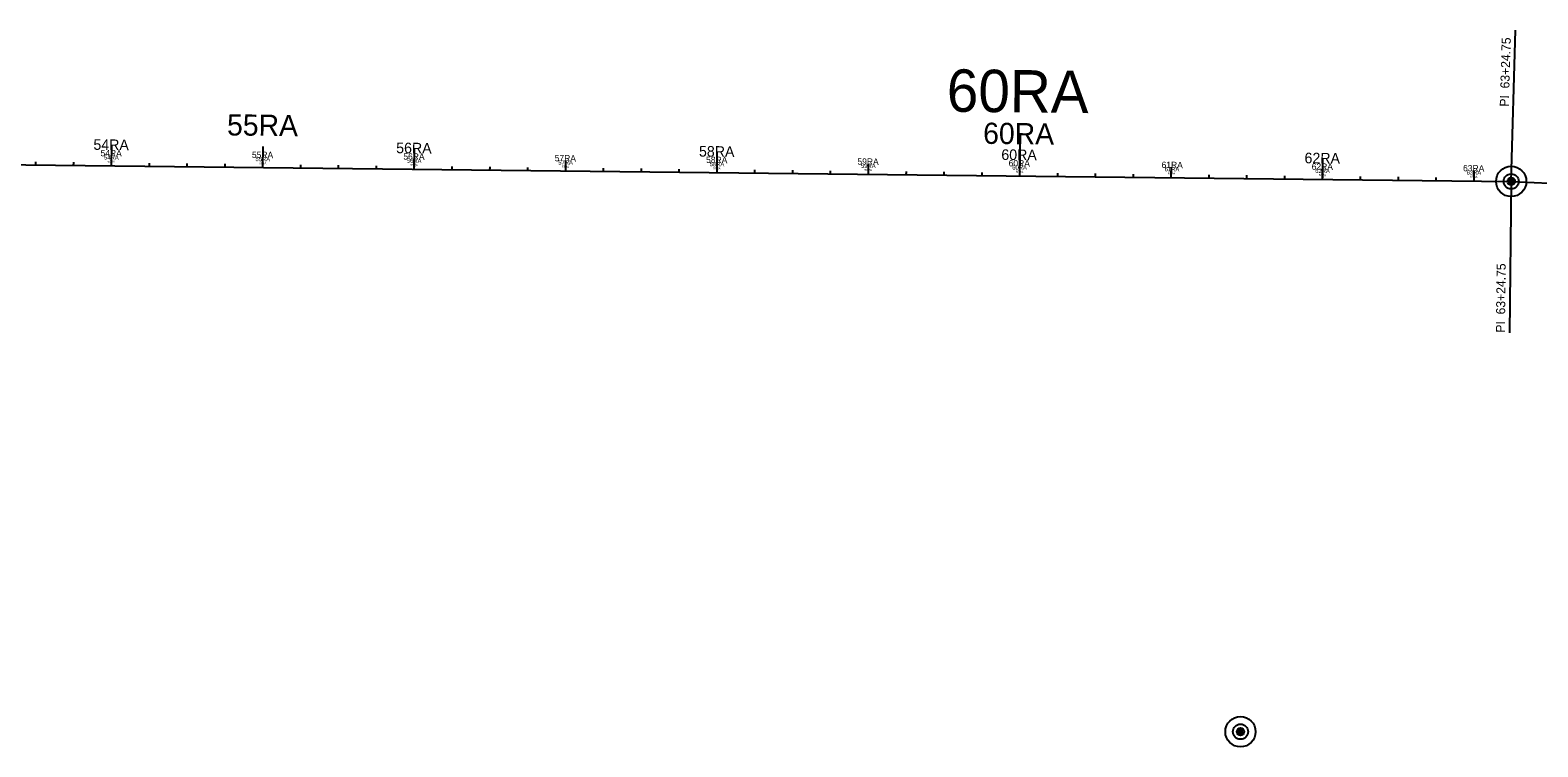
# Model space of a CAD drawing. Extents: x 564646 to 607088, y 225853 to 261760.
# Drawn here: x 599296 to 600292, y 254603 to 255076 of the extents above; entities that cross this region are included whole.
import ezdxf

# ---------------------------------------------------------------- set-up
doc = ezdxf.new("R2010")
doc.units = 0
for name, color, linetype in [('B_CONC_HIDDEN_LT', 7, 'Continuous'), ('B_CONST', 7, 'Continuous'), ('B_EXIST', 7, 'Continuous'), ('B_TEXT', 7, 'Continuous'), ('E-Easements', 7, 'Continuous'), ('E-Property Lines', 7, 'Continuous'), ('E_ALI_100', 7, 'Continuous'), ('E_RW_CorporateLimits', 7, 'Continuous'), ('E_RW_EasementUtility_Text', 7, 'Continuous'), ('E_WTR_FlowLine', 7, 'Continuous'), ('EMCS_SURVEY_PT CODES', 7, 'Continuous'), ('EMCS_SURVEY_PT ELEV', 7, 'Continuous'), ('EMCS_SURVEY_PT NOTES', 7, 'Continuous'), ('Level 33', 7, 'Continuous'), ('P-Easements Floodplain', 7, 'Continuous'), ('P-Easements Temporary', 7, 'Continuous'), ('P_ALI_100_Tic', 7, 'Continuous'), ('P_ALI_20', 7, 'Continuous'), ('P_ALI_50', 7, 'Continuous'), ('P_RW_AccessPreviousProject Txt', 7, 'Continuous'), ('P_RW_EasementPerm', 7, 'Continuous'), ('P_RW_EasementTemp', 7, 'Continuous'), ('P_RW_PropertyConnector', 7, 'Continuous'), ('P_RW_Proposed', 7, 'Continuous'), ('P_WAL', 7, 'Continuous')]:
    doc.layers.add(name, color=color, linetype=linetype)

msp = doc.modelspace()

# ---------------------------------------------------------------- linework, layer by layer
at = {"layer": 'B_CONC_HIDDEN_LT'}
for p, q in [((597615.91, 255005.79), (600274.63, 254976.34)), ((600274.63, 254976.34), (602948.94, 254849.85))]:
    msp.add_line(p, q, dxfattribs=at)
at = {"layer": 'B_CONST'}
for centre in [(600274.63, 254976.34), (600095.84, 254612.72)]:
    msp.add_circle(centre, 1.5, dxfattribs=at)
at = {"layer": 'B_EXIST'}
for centre in [(600274.63, 254976.34), (600095.84, 254612.72)]:
    msp.add_circle(centre, 5, dxfattribs=at)
at = {"layer": 'B_TEXT'}
msp.add_lwpolyline([(600274.63, 254976.34), (600273.52, 254876.35)], dxfattribs=at)
at = {"layer": 'E-Easements'}
for centre in [(600274.63, 254976.34), (600095.84, 254612.72)]:
    msp.add_circle(centre, 2.5, dxfattribs=at)
at = {"layer": 'E_ALI_100'}
for points in [[(599349.96, 254989.38), (599349.93, 254986.58)], [(599299.95, 254988.54), (599299.94, 254987.14)], [(599324.95, 254988.26), (599324.94, 254986.86)], [(599374.95, 254987.71), (599374.93, 254986.31)], [(599399.95, 254987.43), (599399.93, 254986.03)], [(599424.94, 254987.15), (599424.93, 254985.75)], [(599449.96, 254988.27), (599449.93, 254985.48)], [(599474.94, 254986.6), (599474.93, 254985.2)], [(599499.94, 254986.32), (599499.92, 254984.92)], [(599524.94, 254986.04), (599524.92, 254984.64)], [(599549.95, 254987.17), (599549.92, 254984.37)], [(599574.94, 254985.49), (599574.92, 254984.09)], [(599599.93, 254985.21), (599599.92, 254983.81)], [(599624.93, 254984.94), (599624.92, 254983.54)], [(599649.95, 254986.06), (599649.92, 254983.26)], [(599674.93, 254984.38), (599674.91, 254982.98)], [(599699.93, 254984.11), (599699.91, 254982.71)], [(599724.93, 254983.83), (599724.91, 254982.43)], [(599749.94, 254984.95), (599749.91, 254982.15)], [(599774.92, 254983.28), (599774.91, 254981.88)], [(599799.92, 254983), (599799.91, 254981.6)], [(599824.92, 254982.72), (599824.9, 254981.32)], [(599849.93, 254983.84), (599849.9, 254981.04)], [(599874.92, 254982.17), (599874.9, 254980.77)], [(599899.92, 254981.89), (599899.9, 254980.49)], [(599924.91, 254981.61), (599924.9, 254980.21)], [(599949.93, 254982.74), (599949.9, 254979.94)], [(599974.91, 254981.06), (599974.9, 254979.66)], [(599999.91, 254980.78), (599999.89, 254979.38)], [(600024.91, 254980.51), (600024.89, 254979.11)], [(600049.92, 254981.63), (600049.89, 254978.83)], [(600074.9, 254979.95), (600074.89, 254978.55)], [(600099.9, 254979.68), (600099.89, 254978.28)], [(600124.9, 254979.4), (600124.89, 254978)], [(600149.92, 254980.52), (600149.88, 254977.72)], [(600174.9, 254978.84), (600174.88, 254977.44)], [(600249.91, 254979.41), (600249.88, 254976.61)], [(600199.9, 254978.57), (600199.88, 254977.17)], [(600224.9, 254978.29), (600224.88, 254976.89)], [(600274.94, 254977.73), (600274.88, 254976.33)]]:
    msp.add_lwpolyline(points, dxfattribs=at)
at = {"layer": 'E_WTR_FlowLine'}
for centre in [(600274.63, 254976.34), (600095.84, 254612.72)]:
    msp.add_circle(centre, 0.5, dxfattribs=at)
at = {"layer": 'EMCS_SURVEY_PT CODES'}
for p, q in [((597615.91, 255005.79), (600274.63, 254976.34)), ((600274.63, 254976.34), (602948.94, 254849.85))]:
    msp.add_line(p, q, dxfattribs=at)
at = {"layer": 'EMCS_SURVEY_PT ELEV'}
for p, q in [((597615.91, 255005.79), (600274.63, 254976.34)), ((600274.63, 254976.34), (602948.94, 254849.85))]:
    msp.add_line(p, q, dxfattribs=at)
at = {"layer": 'Level 33'}
for points in [[(599299.94, 254987.84), (599299.94, 254987.14)], [(599324.94, 254987.56), (599324.94, 254986.86)], [(599349.95, 254987.98), (599349.93, 254986.58)], [(599374.94, 254987.01), (599374.93, 254986.31)], [(599399.94, 254986.73), (599399.93, 254986.03)], [(599424.94, 254986.45), (599424.93, 254985.75)], [(599449.94, 254986.87), (599449.93, 254985.48)], [(599474.93, 254985.9), (599474.93, 254985.2)], [(599499.93, 254985.62), (599499.92, 254984.92)], [(599524.93, 254985.34), (599524.92, 254984.64)], [(599549.94, 254985.77), (599549.92, 254984.37)], [(599574.93, 254984.79), (599574.92, 254984.09)], [(599599.93, 254984.51), (599599.92, 254983.81)], [(599624.92, 254984.24), (599624.92, 254983.54)], [(599649.93, 254984.66), (599649.92, 254983.26)], [(599674.92, 254983.68), (599674.91, 254982.98)], [(599699.92, 254983.41), (599699.91, 254982.71)], [(599724.92, 254983.13), (599724.91, 254982.43)], [(599749.92, 254983.55), (599749.91, 254982.15)], [(599774.92, 254982.58), (599774.91, 254981.88)], [(599799.91, 254982.3), (599799.91, 254981.6)], [(599824.91, 254982.02), (599824.9, 254981.32)], [(599849.92, 254982.44), (599849.9, 254981.04)], [(599874.91, 254981.47), (599874.9, 254980.77)], [(599899.91, 254981.19), (599899.9, 254980.49)], [(599924.91, 254980.91), (599924.9, 254980.21)], [(599949.91, 254981.34), (599949.9, 254979.94)], [(599974.9, 254980.36), (599974.9, 254979.66)], [(599999.9, 254980.08), (599999.89, 254979.38)], [(600024.9, 254979.81), (600024.89, 254979.11)], [(600049.91, 254980.23), (600049.89, 254978.83)], [(600074.9, 254979.25), (600074.89, 254978.55)], [(600099.9, 254978.98), (600099.89, 254978.28)], [(600149.9, 254979.12), (600149.88, 254977.72)], [(600124.89, 254978.7), (600124.89, 254978)], [(600174.89, 254978.14), (600174.88, 254977.44)], [(600199.89, 254977.87), (600199.88, 254977.17)], [(600224.89, 254977.59), (600224.88, 254976.89)], [(600249.89, 254978.01), (600249.88, 254976.61)], [(600274.91, 254977.03), (600274.88, 254976.33)]]:
    msp.add_lwpolyline(points, dxfattribs=at)
at = {"layer": 'P-Easements Floodplain'}
for p, q in [((597615.91, 255005.79), (600274.63, 254976.34)), ((600274.63, 254976.34), (602948.94, 254849.85))]:
    msp.add_line(p, q, dxfattribs=at)
at = {"layer": 'P-Easements Temporary'}
for centre in [(600274.63, 254976.34), (600095.84, 254612.72)]:
    msp.add_circle(centre, 10, dxfattribs=at)
at = {"layer": 'P_ALI_100_Tic'}
for points in [[(599350.09, 255000.58), (599349.93, 254986.58)], [(599950.21, 255007.94), (599949.9, 254979.94)], [(599550.08, 254998.37), (599549.92, 254984.37)], [(599750.06, 254996.15), (599749.91, 254982.15)], [(600150.04, 254991.72), (600149.88, 254977.72)]]:
    msp.add_lwpolyline(points, dxfattribs=at)
at = {"layer": 'P_ALI_20'}
for points in [[(599450.08, 254999.47), (599449.93, 254985.48)], [(599350.01, 254993.58), (599349.93, 254986.58)], [(599550, 254991.37), (599549.92, 254984.37)], [(599649.99, 254990.26), (599649.92, 254983.26)], [(599749.99, 254989.15), (599749.91, 254982.15)], [(599950.05, 254993.94), (599949.9, 254979.94)], [(599849.98, 254988.04), (599849.9, 254981.04)], [(600049.97, 254985.83), (600049.89, 254978.83)], [(600149.96, 254984.72), (600149.88, 254977.72)], [(600249.96, 254983.61), (600249.88, 254976.61)]]:
    msp.add_lwpolyline(points, dxfattribs=at)
at = {"layer": 'P_ALI_50'}
msp.add_lwpolyline([(600274.63, 254976.34), (600277.55, 255076.3)], dxfattribs=at)
at = {"layer": 'P_RW_AccessPreviousProject Txt'}
for points in [[(599299.96, 254989.24), (599299.94, 254987.14)], [(599324.96, 254988.96), (599324.94, 254986.86)], [(599349.98, 254990.78), (599349.93, 254986.58)], [(599449.97, 254989.67), (599449.93, 254985.48)], [(599374.96, 254988.41), (599374.93, 254986.31)], [(599399.95, 254988.13), (599399.93, 254986.03)], [(599424.95, 254987.85), (599424.93, 254985.75)], [(599474.95, 254987.3), (599474.93, 254985.2)], [(599499.95, 254987.02), (599499.92, 254984.92)], [(599524.95, 254986.74), (599524.92, 254984.64)], [(599549.97, 254988.57), (599549.92, 254984.37)], [(599574.94, 254986.19), (599574.92, 254984.09)], [(599599.94, 254985.91), (599599.92, 254983.81)], [(599624.94, 254985.64), (599624.92, 254983.54)], [(599649.96, 254987.46), (599649.92, 254983.26)], [(599674.94, 254985.08), (599674.91, 254982.98)], [(599699.94, 254984.81), (599699.91, 254982.71)], [(599724.93, 254984.53), (599724.91, 254982.43)], [(599749.96, 254986.35), (599749.91, 254982.15)], [(599774.93, 254983.98), (599774.91, 254981.88)], [(599799.93, 254983.7), (599799.91, 254981.6)], [(599824.93, 254983.42), (599824.9, 254981.32)], [(599849.95, 254985.24), (599849.9, 254981.04)], [(599874.92, 254982.87), (599874.9, 254980.77)], [(599899.92, 254982.59), (599899.9, 254980.49)], [(599924.92, 254982.31), (599924.9, 254980.21)], [(599949.94, 254984.14), (599949.9, 254979.94)], [(599974.92, 254981.76), (599974.9, 254979.66)], [(599999.92, 254981.48), (599999.89, 254979.38)], [(600024.92, 254981.21), (600024.89, 254979.11)], [(600049.94, 254983.03), (600049.89, 254978.83)], [(600074.91, 254980.65), (600074.89, 254978.55)], [(600099.91, 254980.38), (600099.89, 254978.28)], [(600124.91, 254980.1), (600124.89, 254978)], [(600149.93, 254981.92), (600149.88, 254977.72)], [(600174.91, 254979.54), (600174.88, 254977.44)], [(600199.9, 254979.27), (600199.88, 254977.17)], [(600224.9, 254978.99), (600224.88, 254976.89)], [(600249.92, 254980.81), (600249.88, 254976.61)], [(600274.98, 254978.43), (600274.88, 254976.33)]]:
    msp.add_lwpolyline(points, dxfattribs=at)
at = {"layer": 'P_RW_EasementPerm'}
for points in [[(599350.01, 254993.58), (599349.93, 254986.58)], [(599449.97, 254988.97), (599449.93, 254985.48)], [(599550, 254991.37), (599549.92, 254984.37)], [(599749.99, 254989.15), (599749.91, 254982.15)], [(599649.95, 254986.76), (599649.92, 254983.26)], [(599849.94, 254984.54), (599849.9, 254981.04)], [(599949.97, 254986.94), (599949.9, 254979.94)], [(600049.93, 254982.33), (600049.89, 254978.83)], [(600149.96, 254984.72), (600149.88, 254977.72)], [(600249.92, 254980.11), (600249.88, 254976.61)]]:
    msp.add_lwpolyline(points, dxfattribs=at)
at = {"layer": 'P_RW_EasementTemp'}
for p, q in [((597615.91, 255005.79), (600274.63, 254976.34)), ((600274.63, 254976.34), (602948.94, 254849.85))]:
    msp.add_line(p, q, dxfattribs=at)
at = {"layer": 'P_RW_PropertyConnector'}
for p, q in [((597615.91, 255005.79), (600274.63, 254976.34)), ((600274.63, 254976.34), (602948.94, 254849.85))]:
    msp.add_line(p, q, dxfattribs=at)
at = {"layer": 'P_WAL'}
for centre in [(600274.63, 254976.34), (600095.84, 254612.72)]:
    msp.add_circle(centre, 1, dxfattribs=at)

# ---------------------------------------------------------------- texts
for s, p in [('54RA', (599345.23, 254990.84)), ('55RA', (599445.22, 254989.73)), ('56RA', (599545.22, 254988.62)), ('57RA', (599645.21, 254987.51)), ('58RA', (599745.2, 254986.4)), ('59RA', (599845.18, 254985.3)), ('60RA', (599945.08, 254984.19)), ('61RA', (600045.76, 254983.08)), ('62RA', (600145.18, 254981.97)), ('63RA', (600245.17, 254980.87))]:
    msp.add_text(s, height=2.8, rotation=359.36537).set_placement(p)
at = {"layer": 'B_TEXT'}
msp.add_text('PI  63+24.75', height=6, rotation=89.36537, dxfattribs=at).set_placement((600270.52, 254876.38))
at = {"layer": 'E-Property Lines'}
msp.add_text('60RA', height=28, rotation=359.36537, dxfattribs=at).set_placement((599901.75, 255022.47))
at = {"layer": 'E_RW_CorporateLimits'}
for s, p in [('55RA', (599426.41, 255006.74)), ('60RA', (599925.82, 255001.2))]:
    msp.add_text(s, height=14, rotation=359.36537, dxfattribs=at).set_placement(p)
at = {"layer": 'E_RW_EasementUtility_Text'}
for s, p in [('54RA', (599347.58, 254988.71)), ('55RA', (599447.58, 254987.6)), ('56RA', (599547.57, 254986.49)), ('57RA', (599647.56, 254985.39)), ('58RA', (599747.56, 254984.28)), ('59RA', (599847.54, 254983.17)), ('60RA', (599947.49, 254982.06)), ('61RA', (600047.83, 254980.95)), ('62RA', (600147.53, 254979.85)), ('63RA', (600247.53, 254978.74))]:
    msp.add_text(s, height=1.4, rotation=359.36537, dxfattribs=at).set_placement(p)
at = {"layer": 'EMCS_SURVEY_PT NOTES'}
for s, p in [('54RA', (599342.88, 254992.96)), ('55RA', (599442.87, 254991.85)), ('56RA', (599542.87, 254990.75)), ('57RA', (599642.86, 254989.64)), ('58RA', (599742.85, 254988.53)), ('59RA', (599842.81, 254987.42)), ('60RA', (599942.68, 254986.32)), ('61RA', (600043.69, 254985.2)), ('62RA', (600142.83, 254984.1)), ('63RA', (600242.82, 254982.99))]:
    msp.add_text(s, height=4.2, rotation=359.36537, dxfattribs=at).set_placement(p)
at = {"layer": 'P_ALI_50'}
msp.add_text('PI  63+24.75', height=6, rotation=88.3287, dxfattribs=at).set_placement((600273.07, 255025.67))
at = {"layer": 'P_RW_Proposed'}
for s, p in [('54RA', (599338.17, 254997.21)), ('56RA', (599538.16, 254995)), ('58RA', (599738.15, 254992.78)), ('60RA', (599937.86, 254990.57)), ('62RA', (600138.12, 254988.35))]:
    msp.add_text(s, height=7, rotation=359.36537, dxfattribs=at).set_placement(p)

doc.saveas('drawing.dxf')
